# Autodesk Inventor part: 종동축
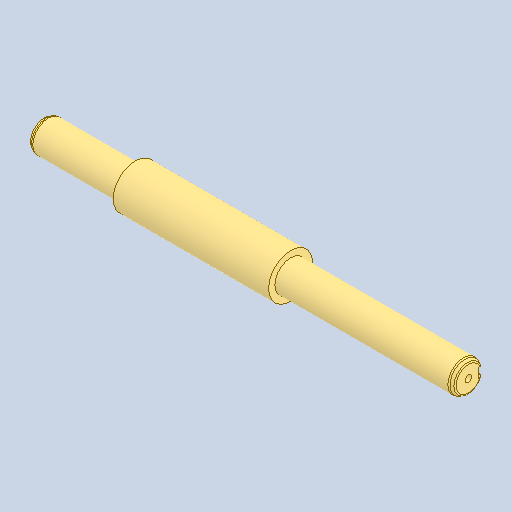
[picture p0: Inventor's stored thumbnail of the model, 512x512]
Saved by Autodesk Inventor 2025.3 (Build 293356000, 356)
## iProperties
Created: 2026-01
Part Number: 종동축
Material: 강철, 탄소
Document SubType Name: Modeling
Designer: PC-13
Density: 7.85 g/cm^3
Appearance: 기본값
Author: jhkim
Sending System: Autodesk Inventor 2026
Preprocessor: ST-DEVELOPER v20.1
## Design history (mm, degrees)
feature "솔리드1"
node "솔리드2"
